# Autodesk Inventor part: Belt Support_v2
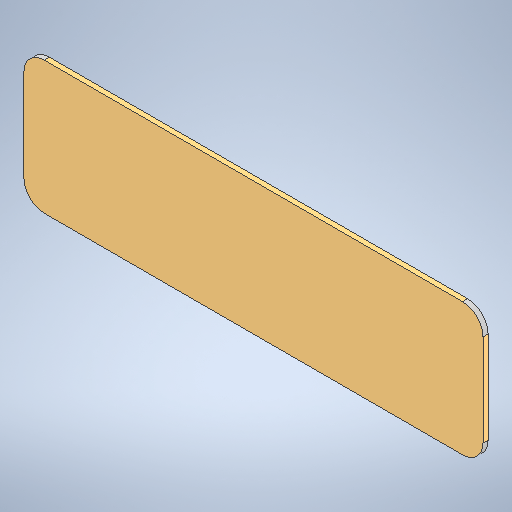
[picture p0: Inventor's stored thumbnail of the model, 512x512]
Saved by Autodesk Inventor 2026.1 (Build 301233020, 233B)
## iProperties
Created: 2026-10
Part Number: Belt Support_v2
Material: Generic
Document SubType Name: Modeling
Designer: hp
Density: 1 g/cm^3
Appearance: Default
Author: hp
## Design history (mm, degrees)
sketch "Sketch1"
  geometry: L1 (0, 0)-(450, 0); L2 (450, 0)-(450, 130); L3 (450, 130)-(0, 130); L4 (0, 130)-(0, 0)
  constraints: 8 end point, 2 parallel, 1 horizontal, 1 perpendicular
  dimensions: "d0" = 450 distance of L3.end L2.end; "d1" = 130 distance of L2.end L1.end
extrude "Extrusion1" new body sketch "Sketch1" distance "d2" = 5; taper "d3" = 0 deg
fillet "Fillet1" dims "d4" = 20
body "Solid1"
